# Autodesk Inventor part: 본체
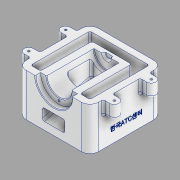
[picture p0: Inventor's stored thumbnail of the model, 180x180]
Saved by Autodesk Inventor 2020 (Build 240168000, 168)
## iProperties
Created: 2022-03
Part Number: 본체
Material: 알루미늄 6061
Document SubType Name: Modeling
Designer: Administrator
Density: 2.7 g/cm^3
Appearance: 알루미늄 - 평지
Mass: 1023.66 g
Surface Area: 844.892 cm^2
Volume: 379.135 cm^3
Author: Administrator
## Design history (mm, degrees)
sketch "스케치4"
  geometry: L1 (55, -55)-(-55, -55); L2 (-55, -55)-(-55, 55); L3 (-55, 55)-(55, 55); L4 (55, 55)-(55, -55); L5 (55, -55)-(-55, 55); L6 (-55, -55)-(55, 55); 1 further point
  constraints: 12 end point, 2 midpoint, 2 parallel, 1 horizontal, 1 perpendicular
  dimensions: "d0" = 110 distance of L2.end L3.end; "d1" = 110 distance of L1.end L2.end
extrude "돌출1" new body sketch "스케치4" distance "d2" = 65; taper "d3" = 0 deg
sketch "스케치5" dims "d24" = 30
  geometry: L1 (110, 65)-(0, 65) reference; C1 r 19 at (55, 65); 1 further point
  constraints: 1 centre point, 1 midpoint
  dimensions: "d4" = 38 diameter of C1
extrude "돌출2" cut sketch "스케치5" distance "d5" = 80; taper "d6" = 0 deg
sketch "스케치6"
  geometry: L1 (110, 65)-(0, 65) reference; C1 r 28 at (55, 65); 1 further point
  constraints: 1 centre point, 1 midpoint
  dimensions: "d7" = 56 diameter of C1
extrude "돌출3" cut sketch "스케치6" distance "d8" = 8; taper "d9" = 0 deg
sketch "스케치7"
  geometry: L1 (28, -55)-(-28, -55) reference; L2 (0, -55)-(0, 55); L3 (55, 55)-(-55, 55) reference; L4 (19, 25)-(19, -47) reference; L5 (5.191, 29)-(0, 29); L6 (5.191, 29)-(7.5, 25); L7 (-19, 25)-(19, 25) reference; L8 (7.5, 25)-(0, 25); 2 further points
  constraints: 8 end point, 3 midpoint, 2 point on line, 1 perpendicular
  dimensions: "d14" = 120 deg angle of L7 L6; "d15" = 4 distance between parallel lines of L7 L5; "d85" = 15 diameter of L6.end L2
revolve "회전1" sketch "스케치7" stored, may be unused: angle "d16" = 90 deg
sketch "스케치11"
  geometry: L1 (19, 60.532)-(19, 31.425); L2 (19, 31.425)-(-55, 11.597); L3 (-55, 0)-(-55, 65) reference; L4 (19, 60.532)-(-19, 60.532); L5 (-19, 60.532)-(-19, 38.843); L6 (-19, 38.843)-(-55, 29.197); L7 (-55, 65)-(55, 65) reference; L8 (33, 65)-(33, 30); L9 (33, 30)-(-44.949, 9.114); L10 (-44.949, 9.114)-(-44.949, 0); L11 (-55, 0)-(55, 0) reference; L12 (55, 0)-(55, 65) reference; 1 further point
  constraints: 16 end point, 4 point on line, 2 vertical, 1 horizontal, 1 parallel, 1 perpendicular
  dimensions: "d20" = 17 distance between parallel lines of L2 L6; "d21" = 38 distance of L1.start L4.end; "d22" = 36 distance between parallel lines of L3 L5; "d23" = 75 deg angle of L2 L1; "d24" = 30 distance from line of L11 L8.end; "d25" = 22 distance between parallel lines of L12 L8; "d26" = 5 distance between parallel lines of L2 L9
extrude "돌출4" cut sketch "스케치11" stored distance "d27" = 34; taper "d28" = 0 deg
sketch "스케치12"
  geometry: L1 (-45, -45)-(-45, 45); L2 (-45, 45)-(45, 45); L3 (45, 45)-(45, -45); L4 (45, -45)-(30, -45); L5 (30, -45)-(30, 33); L6 (30, 33)-(-30, 33); L7 (-30, 33)-(-30, -45); L8 (-30, -45)-(-45, -45); L9 (-55, 55)-(-55, -55) reference; L10 (-55, -55)-(-28, -55) reference; L11 (28, -55)-(55, -55) reference; L12 (55, -55)-(55, 55) reference; L13 (55, 55)-(-55, 55) reference; 1 further point
  constraints: 16 end point, 6 perpendicular, 2 vertical
  dimensions: "d29" = 10 distance between parallel lines of L9 L1; "d30" = 25 distance between parallel lines of L9 L7; "d31" = 10 distance between parallel lines of L10 L8; "d32" = 10 distance between parallel lines of L11 L4; "d33" = 10 distance between parallel lines of L12 L3; "d34" = 25 distance between parallel lines of L12 L5; "d35" = 10 distance between parallel lines of L13 L2; "d36" = 22 distance between parallel lines of L6 L13
extrude "돌출5" cut sketch "스케치12" extent not by distance; stored distance "d37" = 0; taper "d38" = 0 deg
sketch "스케치13"
  geometry: L1 (33, 65)-(33, 0) reference; L2 (-45, 65)-(-45, 0) reference; L3 (-55, 11.597)-(19, 31.425) reference; L4 (33, 30)-(-45, 9.1); L5 (-45, 9.1)-(-45, 0); L6 (-55, 0)-(55, 0) reference; L7 (-55, 0)-(-55, 65) reference; L8 (-45, 0)-(33, 0); L9 (33, 0)-(33, 30); 2 further points
  constraints: 8 end point, 2 point on line, 1 collinear, 1 horizontal, 1 vertical
  dimensions: "d40" = 30 distance from line of L6 L4.start; "d41" = 10 distance between parallel lines of L7 L5; "d42" = 75 deg angle of L1 L4
extrude "돌출6" cut sketch "스케치13" stored distance "d43" = 60; taper "d44" = 0 deg
sketch "스케치14"
  geometry: L1 (-55, 55)-(-55, -55) reference; L2 (-55, 35)-(-65, 35); L3 (-65, 35)-(-65, 21); L4 (-65, 21)-(-55, 21); L5 (55, 55)-(-55, 55) reference; L6 (-65, -21)-(-55, -21); L7 (-65, -35)-(-55, -35); L8 (-55, -35)-(-55, -21); L9 (-55, 21)-(-55, 35); A1 r 7 centre (-65, -28) between (-65, -21) and (-65, -35); 3 further points
  constraints: 14 end point, 4 perpendicular, 4 point on line, 2 collinear, 2 point on circle, 2 tangent, 1 centre point, 1 horizontal, 1 midpoint, 1 vertical alignment, 3 other
  dimensions: "d45" = 14 distance between parallel lines of L4 L2; "d47" = 27 distance from line of point (-65, 28) L5; "d48" = 65 horizontal distance of point (0, 0) point (-65, 28); "d49" = 14 distance between parallel lines of L7 L6; "d50" = 56 distance of point (-65, 28) A1.centre
extrude "돌출7" join sketch "스케치14" distance "d51" = 20; taper "d52" = 0 deg
sketch "스케치15"
  geometry: L1 (-45, -45)-(-45, 45) reference; L2 (-45, 45)-(45, 45) reference; L3 (45, 45)-(45, -45) reference; L4 (45, -45)-(30, -45) reference; L5 (30, -45)-(30, 33) reference; L6 (30, 33)-(-30, 33) reference; L7 (-30, 33)-(-30, -45) reference; L8 (-30, -45)-(-45, -45) reference; L9 (-7.5, 25)-(-5.191, 29) reference; L10 (-5.191, 29)-(5.191, 29) reference; L11 (5.191, 29)-(7.5, 25) reference; L12 (7.5, 25)-(19, 25) reference; L13 (19, 25)-(19, -47) reference; L14 (19, -47)-(28, -47) reference; L15 (28, -47)-(28, -55) reference; L16 (28, -55)-(55, -55) reference; L17 (55, -55)-(55, 55) reference; L18 (55, 55)-(-55, 55) reference; L19 (-55, 55)-(-55, 35) reference; L20 (-55, 35)-(-65, 35) reference; L21 (-65, 21)-(-55, 21) reference; L22 (-55, 21)-(-55, -21) reference; L23 (-55, -21)-(-65, -21) reference; L24 (-65, -35)-(-55, -35) reference; L25 (-55, -35)-(-55, -55) reference; L26 (-55, -55)-(-28, -55) reference; L27 (-28, -55)-(-28, -47) reference; L28 (-28, -47)-(-19, -47) reference; L29 (-19, -47)-(-19, 25) reference; L30 (-19, 25)-(-7.5, 25) reference; A1 r 7 centre (-65, 28) between (-65, 35) and (-65, 21) reference; A2 r 7 centre (-65, -28) between (-65, -21) and (-65, -35) reference; 1 further point
hole "구멍1" sketch "스케치15" at (-65, 28), (-65, -28) diameter "d53" = 3.242; stored, may be unused: countersink angle "d57" = 90 deg, drill point angle "d59" = 118 deg; dims "d54" = 9, "d55" = 4, "d56" = 2, "d58" = 11
node "작업 평면1"
node "작업 평면2"
sketch "스케치16"
  geometry: L1 (0, 0)-(-65, 0) reference; L2 (0, 0)-(0, 110) reference; 2 further points
  constraints: 1 other
  dimensions: "d61" = 55 distance from line of L1 point (-20, 55); "d62" = 20 distance from line of L2 point (-20, 55)
feature "엠보싱1" sketch "스케치16" dims "d0" = 110, "d1" = 110, "d63" = 0.5, "d64" = 0
fillet "모깎기1" dims "d65" = 13
fillet "모깎기2" dims "d66" = 1
chamfer "모따기1" distance "d67" = 1; stored, may be unused: second distance "d68" = 2, angle "d69" = 45 deg
sketch "스케치17" dims "d14" = 120 deg, "d15" = 4, "d70" = 46, "d85" = 15
  geometry: L1 (85, 65)-(25, 65) reference; 3 further points
  constraints: 1 midpoint, 1 vertical alignment, 2 other
hole "구멍2" sketch "스케치17" at (55, 42) diameter "d71" = 3.242; stored, may be unused: countersink angle "d75" = 90 deg, drill point angle "d77" = 118 deg; dims "d72" = 9, "d73" = 4, "d74" = 2, "d76" = 11
fillet "모깎기3" dims "d78" = 3
fillet "모깎기4" dims "d79" = 3
fillet "모깎기5" dims "d80" = 3
fillet "모깎기6" dims "d81" = 3
fillet "모깎기7" dims "d82" = 3
fillet "모깎기8" dims "d83" = 3
fillet "모깎기9" dims "d84" = 3
fillet "모깎기10" dims "d86" = 1
node "솔리드1"
mirror "미러1"
node "투영된 루프1"
feature "A9D066F2-1C7D-4E18-AEED-F7BC21143FA4" dims "d53" = 3.242, "d54" = 9, "d55" = 4, "d56" = 2, "d57" = 90 deg, "d58" = 11, "d59" = 118 deg
other parameters: "d60" = 63.5
